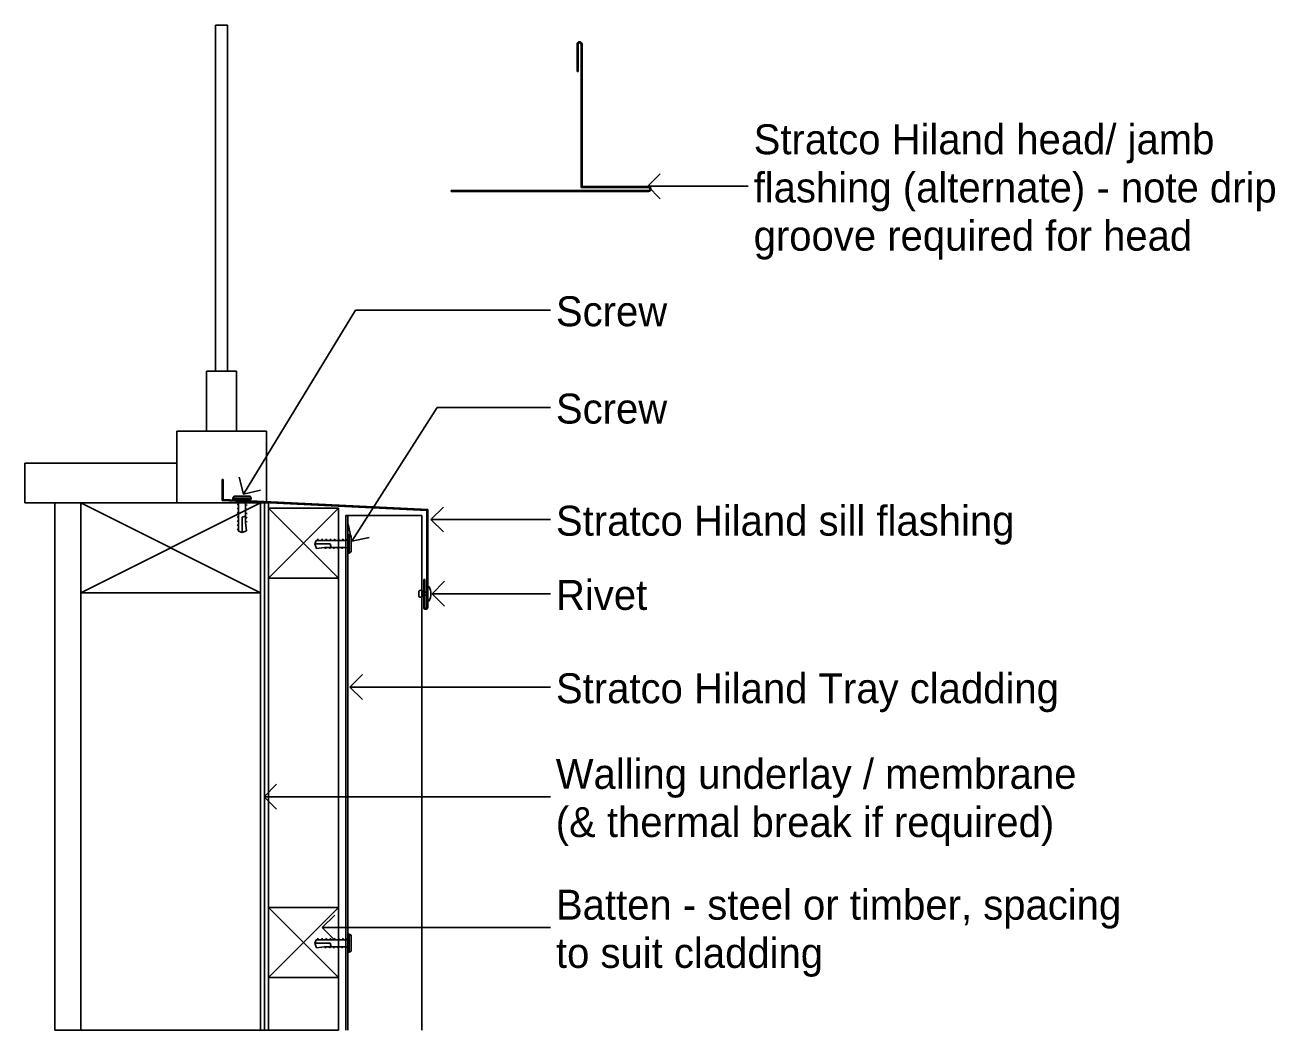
# Model space of a CAD drawing. Extents: x -2.36 to 6.66, y -3.72 to 4.13.
# Drawn here: x -0.54 to 0.086, y 0.566 to 1.069 of the extents above; entities that cross this region are included whole.
import ezdxf

# ---------------------------------------------------------------- set-up
doc = ezdxf.new("R2010")
doc.units = 0
for name, color, linetype in [('A-____-____-IDEN', 7, 'Continuous'), ('A-DETL-____-MEDM', 7, 'Continuous'), ('A-DETL-GENF-OTLN', 7, 'Continuous'), ('A-GLAZ-____-MCUT', 7, 'Continuous'), ('A-GLAZ-____-OTLN', 7, 'Continuous'), ('A-WALL-____-MCUT', 7, 'Continuous'), ('A-WALL-____-PATT', 7, 'Continuous'), ('A-WALL-FNSH-MCUT', 7, 'Continuous')]:
    doc.layers.add(name, color=color, linetype=linetype)

# ---------------------------------------------------------------- blocks, each defined once
blk = doc.blocks.new('Fixed - 1L _AUS_ - 1515-V2-Hiland Nailstrip Opening Head _ Sill')
at = {"layer": 'A-GLAZ-____-MCUT'}
for p, q in [((-2.06153, 1.06942), (-2.06153, 0.896)), ((-2.05553, 0.896), (-2.05553, 1.06942)), ((-2.05103, 0.896), (-2.06603, 0.896)), ((-2.06603, 0.896), (-2.06603, 0.866)), ((-2.06153, 0.896), (-2.05553, 0.896)), ((-2.05103, 0.866), (-2.05103, 0.896)), ((-2.036, 0.866), (-2.081, 0.866)), ((-2.081, 0.866), (-2.081, 0.83)), ((-2.06603, 0.866), (-2.05103, 0.866)), ((-2.036, 0.83), (-2.036, 0.866)), ((-2.081, 0.85), (-2.157, 0.85)), ((-2.157, 0.85), (-2.157, 0.83)), ((-2.081, 0.83), (-2.081, 0.85)), ((-2.157, 0.83), (-2.129, 0.83)), ((-2.039, 0.83), (-2.036, 0.83))]:
    blk.add_line(p, q, dxfattribs=at)
at = {"layer": 'A-GLAZ-____-OTLN'}
for p, q in [((-2.05553, 1.06942), (-2.06153, 1.06942)), ((-2.06153, 1.06942), (-2.06153, 0.896)), ((-2.05553, 0.896), (-2.05553, 1.06942)), ((-2.05103, 0.896), (-2.06603, 0.896)), ((-2.06603, 0.896), (-2.06603, 0.866)), ((-2.06153, 0.896), (-2.05553, 0.896)), ((-2.05103, 0.866), (-2.05103, 0.896)), ((-2.036, 0.866), (-2.081, 0.866)), ((-2.081, 0.866), (-2.081, 0.83)), ((-2.06603, 0.866), (-2.05103, 0.866)), ((-2.036, 0.83), (-2.036, 0.866)), ((-2.081, 0.85), (-2.157, 0.85)), ((-2.157, 0.85), (-2.157, 0.83)), ((-2.081, 0.83), (-2.081, 0.85)), ((-2.157, 0.83), (-2.081, 0.83)), ((-2.081, 0.83), (-2.036, 0.83))]:
    blk.add_line(p, q, dxfattribs=at)
blk = doc.blocks.new('DET_ST_Framing Detail Timber - 45x90-V3-Hiland Nailstrip Opening Head _ Sill')
at = {"layer": 'A-DETL-____-MEDM'}
for p, q in [((-2.039, 0.83), (-2.129, 0.83)), ((-2.129, 0.83), (-2.129, 0.785)), ((-2.039, 0.785), (-2.039, 0.83)), ((-2.129, 0.785), (-2.039, 0.785))]:
    blk.add_line(p, q, dxfattribs=at)
at = {"layer": 'A-DETL-GENF-OTLN'}
for p, q in [((-2.039, 0.785), (-2.129, 0.83)), ((-2.129, 0.785), (-2.039, 0.83))]:
    blk.add_line(p, q, dxfattribs=at)
blk = doc.blocks.new('Detail_Stratco_Hiland_Tray_Sill - Rib Height 38mm-Hiland Nailstrip Opening Head _ Sill')
at = {"layer": 'A-DETL-GENF-OTLN'}
for p, q in [((-2.05775, 0.84175), (-2.05825, 0.84175)), ((-2.05825, 0.84175), (-2.05825, 0.83127)), ((-2.05775, 0.83175), (-2.05775, 0.84175)), ((-1.95575, 0.82627), (-2.05825, 0.83127)), ((-1.95525, 0.82675), (-2.05775, 0.83175)), ((-1.95525, 0.77775), (-1.95525, 0.82675)), ((-1.95575, 0.77775), (-1.95575, 0.82627)), ((-1.95725, 0.77775), (-1.95725, 0.79175)), ((-1.95725, 0.79175), (-1.95675, 0.79175)), ((-1.95675, 0.77775), (-1.95675, 0.79175))]:
    blk.add_line(p, q, dxfattribs=at)
for radius in [0.001, 0.0005]:
    blk.add_arc((-1.95625, 0.77775), radius, 180, 0, dxfattribs=at)
blk = doc.blocks.new('DET_Screw Metal Wafer - DET_Screw Metal Wafer-V4-Hiland Nailstrip Opening Head _ Sill')
at = {"layer": 'A-DETL-GENF-OTLN'}
for p, q in [((-2.05284, 0.83246), (-2.05229, 0.83339)), ((-2.05229, 0.83339), (-2.04428, 0.83339)), ((-2.04428, 0.83339), (-2.04373, 0.83245)), ((-2.04373, 0.83246), (-2.05284, 0.83246)), ((-2.05238, 0.83175), (-2.04418, 0.83175)), ((-2.05003, 0.82916), (-2.05078, 0.8294)), ((-2.05003, 0.82707), (-2.05078, 0.8273)), ((-2.05003, 0.81587), (-2.05003, 0.83095)), ((-2.04653, 0.82015), (-2.04653, 0.83095)), ((-2.04578, 0.82889), (-2.04653, 0.82913)), ((-2.04578, 0.82679), (-2.04653, 0.82703)), ((-2.05003, 0.82497), (-2.05078, 0.82521)), ((-2.05003, 0.82287), (-2.05078, 0.82311)), ((-2.05003, 0.82077), (-2.05078, 0.82101)), ((-2.04828, 0.82285), (-2.04653, 0.82335)), ((-2.04828, 0.81524), (-2.04828, 0.82285)), ((-2.04578, 0.82469), (-2.04653, 0.82493)), ((-2.04578, 0.8226), (-2.04653, 0.82283)), ((-2.04578, 0.8205), (-2.04653, 0.82073)), ((-2.05003, 0.81867), (-2.05078, 0.81891)), ((-2.05003, 0.81657), (-2.05078, 0.81681)), ((-2.05003, 0.81587), (-2.04828, 0.81524)), ((-2.04596, 0.81608), (-2.04828, 0.81524)), ((-2.04653, 0.82015), (-2.04596, 0.81608))]:
    blk.add_line(p, q, dxfattribs=at)
for centre, radius, start, end in [((-2.05238, 0.83225), 0.0005, 156.33018, 270), ((-2.05083, 0.83095), 0.0008, 0, 90), ((-2.04573, 0.83095), 0.0008, 90, 180), ((-2.04418, 0.83225), 0.0005, 270, 23.66982)]:
    blk.add_arc(centre, radius, start, end, dxfattribs=at)
blk = doc.blocks.new('DET_Rivet - DET_Rivet-Hiland Nailstrip Opening Head _ Sill')
at = {"layer": 'A-DETL-GENF-OTLN'}
for p, q in [((-1.99969, 1.42846), (-1.99969, 1.42696)), ((-1.99769, 1.42846), (-1.99599, 1.42846)), ((-1.99769, 1.42696), (-1.99769, 1.42846)), ((-1.99519, 1.43081), (-1.99519, 1.42926)), ((-1.99519, 1.42616), (-1.99519, 1.42926)), ((-1.99769, 1.42696), (-1.99599, 1.42696)), ((-1.99519, 1.42616), (-1.99519, 1.42461))]:
    blk.add_line(p, q, dxfattribs=at)
for centre, radius, start, end in [((-1.99869, 1.42846), 0.001, 0, 180), ((-1.99599, 1.42926), 0.0008, 270, 0), ((-1.99469, 1.43081), 0.0005, 52.97797, 180), ((-2.00205, 1.42771), 0.00842, 335.4444, 24.5556), ((-1.99869, 1.42696), 0.001, 180, 0), ((-1.99599, 1.42616), 0.0008, 0, 90), ((-1.99469, 1.42461), 0.0005, 180, 307.02203)]:
    blk.add_arc(centre, radius, start, end, dxfattribs=at)
blk = doc.blocks.new('Detail_Stratco_Cladding Side Profile - 38mm-V5-Hiland Nailstrip Opening Head _ Sill')
at = {"layer": 'A-DETL-____-MEDM'}
for p, q in [((-1.99628, 0.82375), (-1.99628, 0.56603)), ((-1.99528, 0.82375), (-1.99628, 0.82375)), ((-1.99528, 0.56603), (-1.99528, 0.82375))]:
    blk.add_line(p, q, dxfattribs=at)
at = {"layer": 'A-DETL-GENF-OTLN'}
for p, q in [((-1.95828, 0.82375), (-1.99628, 0.82375)), ((-1.95828, 0.56603), (-1.95828, 0.82375))]:
    blk.add_line(p, q, dxfattribs=at)
blk = doc.blocks.new('DET_ST_Framing Detail Timber - 35x35 Batten-V6-Hiland Nailstrip Opening Head _ Sill')
at = {"layer": 'A-DETL-____-MEDM'}
for p, q in [((-2, 0.827375), (-2.035, 0.827375)), ((-2.035, 0.827375), (-2.035, 0.792375)), ((-2, 0.792375), (-2, 0.827375)), ((-2.035, 0.792375), (-2, 0.792375))]:
    blk.add_line(p, q, dxfattribs=at)
at = {"layer": 'A-DETL-GENF-OTLN'}
for p, q in [((-2, 0.792375), (-2.035, 0.827375)), ((-2.035, 0.792375), (-2, 0.827375))]:
    blk.add_line(p, q, dxfattribs=at)
blk = doc.blocks.new('Detail_Stratco_Hiland_Tray_Head Jamb - Rib Height 38mm-Hiland Nailstrip Opening Head _ Sill')
at = {"layer": 'A-DETL-GENF-OTLN'}
for p, q in [((-1.88045, 1.04605), (-1.88045, 1.0598)), ((-1.87995, 1.04605), (-1.87995, 1.0598)), ((-1.87845, 0.98805), (-1.87845, 1.0598)), ((-1.87795, 0.98855), (-1.87795, 1.0598)), ((-1.88045, 1.04605), (-1.87995, 1.04605)), ((-1.94345, 0.98605), (-1.94345, 0.98655)), ((-1.8447, 0.98655), (-1.94345, 0.98655)), ((-1.8447, 0.98605), (-1.94345, 0.98605)), ((-1.87845, 0.98805), (-1.8447, 0.98805)), ((-1.87795, 0.98855), (-1.8447, 0.98855))]:
    blk.add_line(p, q, dxfattribs=at)
for centre, radius, start, end in [((-1.8792, 1.0598), 0.00125, 0, 180), ((-1.8792, 1.0598), 0.00075, 0, 180), ((-1.8447, 0.9873), 0.00125, 270, 90), ((-1.8447, 0.9873), 0.00075, 270, 90)]:
    blk.add_arc(centre, radius, start, end, dxfattribs=at)
blk = doc.blocks.new('DET_Screw Metal Wafer - DET_Screw Metal Wafer-V7-Hiland Nailstrip Opening Head _ Sill')
at = {"layer": 'A-DETL-GENF-OTLN'}
for p, q in [((-2.01116, 0.81125), (-2.01179, 0.8095)), ((-2.01179, 0.8095), (-2.00418, 0.8095)), ((-2.01095, 0.80718), (-2.01179, 0.8095)), ((-2.01116, 0.81125), (-1.99608, 0.81125)), ((-2.01046, 0.81125), (-2.01022, 0.812)), ((-2.00836, 0.81125), (-2.00812, 0.812)), ((-2.00626, 0.81125), (-2.00602, 0.812)), ((-2.00418, 0.8095), (-2.00368, 0.80775)), ((-2.00416, 0.81125), (-2.00392, 0.812)), ((-2.00206, 0.81125), (-2.00183, 0.812)), ((-1.99997, 0.81125), (-1.99973, 0.812)), ((-1.99787, 0.81125), (-1.99763, 0.812)), ((-1.99528, 0.8136), (-1.99528, 0.8054)), ((-1.99457, 0.81405), (-1.99364, 0.8135)), ((-1.99457, 0.80495), (-1.99457, 0.81405)), ((-1.99364, 0.8135), (-1.99364, 0.80549)), ((-2.00688, 0.80775), (-2.01095, 0.80718)), ((-2.00688, 0.80775), (-1.99608, 0.80775)), ((-2.00653, 0.807), (-2.0063, 0.80775)), ((-2.00444, 0.807), (-2.0042, 0.80775)), ((-2.00234, 0.807), (-2.0021, 0.80775)), ((-2.00024, 0.807), (-2, 0.80775)), ((-1.99814, 0.807), (-1.9979, 0.80775)), ((-1.99364, 0.80549), (-1.99458, 0.80494))]:
    blk.add_line(p, q, dxfattribs=at)
for centre, radius, start, end in [((-1.99478, 0.8136), 0.0005, 66.33018, 180), ((-1.99608, 0.81205), 0.0008, 270, 0), ((-1.99608, 0.80695), 0.0008, 0, 90), ((-1.99478, 0.8054), 0.0005, 180, 293.66982)]:
    blk.add_arc(centre, radius, start, end, dxfattribs=at)

msp = doc.modelspace()

# ---------------------------------------------------------------- linework, layer by layer
at = {"layer": 'A-____-____-IDEN'}
for p, q in [((-0.228, 0.98863), (-0.22175, 0.99488)), ((-0.228, 0.98863), (-0.22175, 0.98238)), ((-0.228, 0.98863), (-0.21511, 0.98863)), ((-0.21511, 0.98863), (-0.17768, 0.98863)), ((-0.43063, 0.83435), (-0.37448, 0.92664)), ((-0.37448, 0.92664), (-0.27673, 0.92664)), ((-0.37622, 0.81085), (-0.33356, 0.87789)), ((-0.33356, 0.87789), (-0.27673, 0.87789)), ((-0.43063, 0.83435), (-0.43272, 0.84294)), ((-0.43063, 0.83435), (-0.42204, 0.83644)), ((-0.33665, 0.82173), (-0.3304, 0.82798)), ((-0.33665, 0.82173), (-0.3304, 0.81548)), ((-0.33665, 0.82173), (-0.27673, 0.82173)), ((-0.37622, 0.81085), (-0.37813, 0.81948)), ((-0.37622, 0.81085), (-0.36759, 0.81276)), ((-0.33603, 0.78455), (-0.32978, 0.7908)), ((-0.33603, 0.78455), (-0.32978, 0.7783)), ((-0.33603, 0.78455), (-0.32605, 0.78455)), ((-0.32605, 0.78455), (-0.27673, 0.78455)), ((-0.37722, 0.73781), (-0.37097, 0.74406)), ((-0.37722, 0.73781), (-0.37097, 0.73156)), ((-0.37722, 0.73781), (-0.36662, 0.73781)), ((-0.36662, 0.73781), (-0.27673, 0.73781)), ((-0.42025, 0.68285), (-0.414, 0.6891)), ((-0.42025, 0.68285), (-0.414, 0.6766)), ((-0.42025, 0.68285), (-0.4037, 0.68285)), ((-0.4037, 0.68285), (-0.27673, 0.68285)), ((-0.39112, 0.61731), (-0.38487, 0.62356)), ((-0.39112, 0.61731), (-0.38487, 0.61106)), ((-0.39112, 0.61731), (-0.37448, 0.61731)), ((-0.37448, 0.61731), (-0.27673, 0.61731))]:
    msp.add_line(p, q, dxfattribs=at)
at = {"layer": 'A-WALL-____-MCUT'}
for p, q in [((-0.41801, 0.83), (-0.42201, 0.83)), ((-0.42001, 0.83), (-0.42001, 0.56603)), ((-0.41801, 0.83), (-0.41801, 0.82737)), ((-0.41801, 0.79237), (-0.41801, 0.62737)), ((-0.38301, 0.62737), (-0.38301, 0.79237)), ((-0.51201, 0.785), (-0.51201, 0.56603)), ((-0.42201, 0.785), (-0.42201, 0.56603)), ((-0.41801, 0.59237), (-0.41801, 0.56603)), ((-0.38301, 0.56603), (-0.38301, 0.59237))]:
    msp.add_line(p, q, dxfattribs=at)
at = {"layer": 'A-WALL-____-PATT'}
for p, q in [((-0.51201, 0.83), (-0.52501, 0.83)), ((-0.52501, 0.83), (-0.52501, 0.56603)), ((-0.51201, 0.56603), (-0.51201, 0.83)), ((-0.42001, 0.83), (-0.42201, 0.83)), ((-0.42201, 0.83), (-0.42201, 0.785)), ((-0.42001, 0.56603), (-0.42001, 0.83)), ((-0.41801, 0.83), (-0.42001, 0.83)), ((-0.42001, 0.83), (-0.42001, 0.56603)), ((-0.41801, 0.56603), (-0.41801, 0.83)), ((-0.38301, 0.79237), (-0.41801, 0.79237)), ((-0.41801, 0.79237), (-0.41801, 0.62737)), ((-0.38301, 0.62737), (-0.38301, 0.79237)), ((-0.42201, 0.785), (-0.51201, 0.785)), ((-0.51201, 0.785), (-0.51201, 0.56603)), ((-0.42201, 0.56603), (-0.42201, 0.785)), ((-0.42201, 0.785), (-0.42201, 0.56603)), ((-0.41801, 0.62737), (-0.39122, 0.62737)), ((-0.39122, 0.62737), (-0.38301, 0.62737)), ((-0.38301, 0.59237), (-0.41801, 0.59237)), ((-0.41801, 0.59237), (-0.41801, 0.56603)), ((-0.38301, 0.56603), (-0.38301, 0.59237)), ((-0.52501, 0.56603), (-0.51201, 0.56603)), ((-0.51201, 0.56603), (-0.42201, 0.56603)), ((-0.42201, 0.56603), (-0.42001, 0.56603)), ((-0.42001, 0.56603), (-0.41801, 0.56603)), ((-0.41801, 0.56603), (-0.38301, 0.56603))]:
    msp.add_line(p, q, dxfattribs=at)
at = {"layer": 'A-WALL-FNSH-MCUT'}
for p, q in [((-0.52501, 0.83), (-0.52501, 0.56603)), ((-0.51201, 0.83), (-0.52501, 0.83))]:
    msp.add_line(p, q, dxfattribs=at)

# ---------------------------------------------------------------- block references
at = {"layer": 'A-DETL-GENF-OTLN'}
for name, p in [('Detail_Stratco_Hiland_Tray_Head Jamb - Rib Height 38mm-Hiland Nailstrip Opening Head _ Sill', (1.61699, 0)), ('Detail_Stratco_Hiland_Tray_Sill - Rib Height 38mm-Hiland Nailstrip Opening Head _ Sill', (1.61699, 0)), ('DET_Screw Metal Wafer - DET_Screw Metal Wafer-V4-Hiland Nailstrip Opening Head _ Sill', (1.61699, 0)), ('DET_ST_Framing Detail Timber - 45x90-V3-Hiland Nailstrip Opening Head _ Sill', (1.61699, 0)), ('DET_ST_Framing Detail Timber - 35x35 Batten-V6-Hiland Nailstrip Opening Head _ Sill', (1.61699, 0)), ('Detail_Stratco_Cladding Side Profile - 38mm-V5-Hiland Nailstrip Opening Head _ Sill', (1.61699, 0)), ('DET_Screw Metal Wafer - DET_Screw Metal Wafer-V7-Hiland Nailstrip Opening Head _ Sill', (1.61699, 0)), ('DET_Rivet - DET_Rivet-Hiland Nailstrip Opening Head _ Sill', (1.65693, -0.6432)), ('DET_ST_Framing Detail Timber - 35x35 Batten-V6-Hiland Nailstrip Opening Head _ Sill', (1.61699, -0.2)), ('DET_Screw Metal Wafer - DET_Screw Metal Wafer-V7-Hiland Nailstrip Opening Head _ Sill', (1.61699, -0.2))]:
    msp.add_blockref(name, p, dxfattribs=at)
at = {"layer": 'A-GLAZ-____-OTLN'}
msp.add_blockref('Fixed - 1L _AUS_ - 1515-V2-Hiland Nailstrip Opening Head _ Sill', (1.61699, 0), dxfattribs=at)

# ---------------------------------------------------------------- texts
at = {"layer": 'A-____-____-IDEN'}
for s, p in [('Stratco Hiland head/ jamb', (-0.17497, 1.00468)), ('flashing (alternate) - note drip', (-0.17497, 0.98054)), ('groove required for head', (-0.17497, 0.9564)), ('Screw', (-0.27401, 0.91854)), ('Screw', (-0.27401, 0.86979)), ('Stratco Hiland sill flashing', (-0.27401, 0.81363)), ('Rivet', (-0.27401, 0.77645)), ('Stratco Hiland Tray cladding', (-0.27401, 0.72971)), ('Walling underlay / membrane', (-0.27412, 0.68683)), ('(& thermal break if required)', (-0.27412, 0.66269)), ('Batten - steel or timber, spacing', (-0.27401, 0.62128)), ('to suit cladding', (-0.27401, 0.59714))]:
    msp.add_text(s, height=0.015, dxfattribs=at).set_placement(p)

doc.saveas('drawing.dxf')
